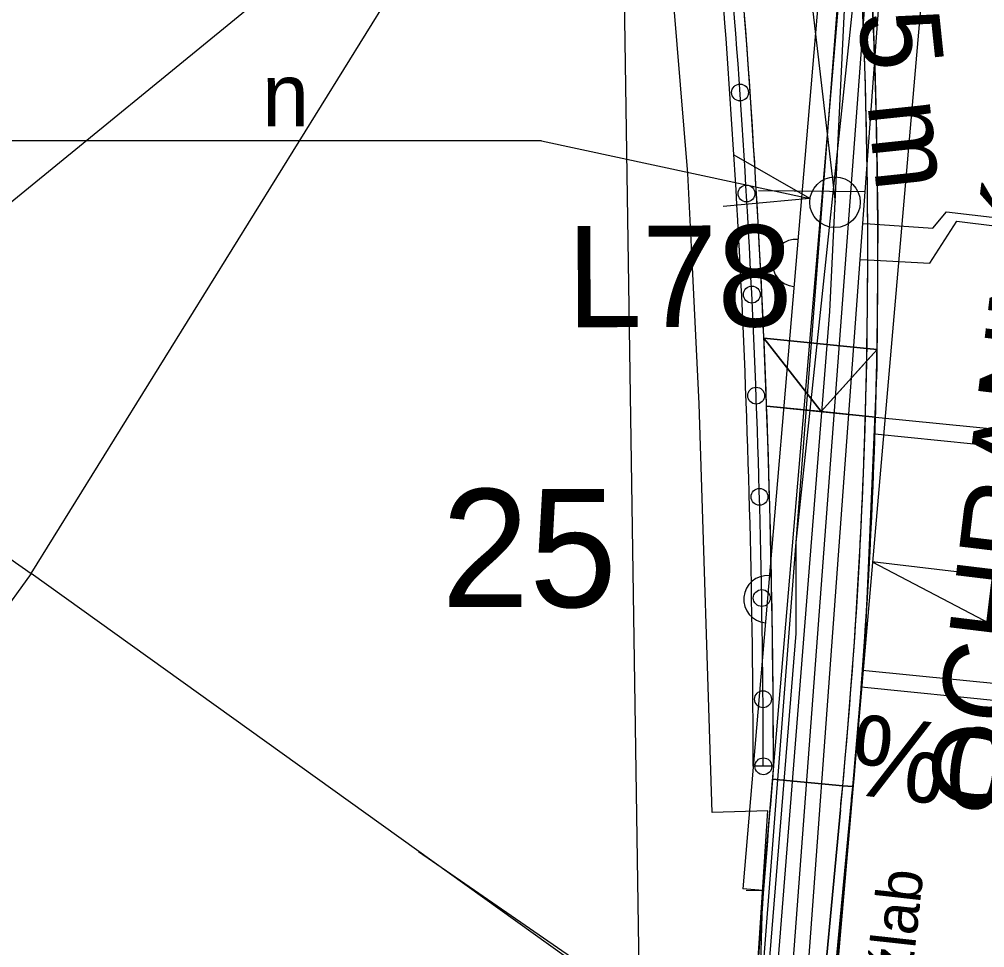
# Model space of a CAD drawing. Extents: x -643342 to -638635, y -1201752 to -1189948.
# Drawn here: x -639509.69 to -639495.38, y -1192753.31 to -1192739.55 of the extents above; entities that cross this region are included whole.
import ezdxf

# ---------------------------------------------------------------- set-up
doc = ezdxf.new("R2010")
doc.units = 0
for name, color, linetype in [('2', 7, 'Continuous'), ('42', 7, 'Continuous'), ('IS_EL_NN_NADZEMNÍ', 7, 'Continuous'), ('IS_EL_NN_PODZEMNÍ', 7, 'Continuous'), ('IS_PLYN_STL', 7, 'Continuous'), ('IS_TELEF_MISTNI_ZAMERENO', 7, 'Continuous'), ('IS_VODOVOD_PRIPOJKA DOMOVNÍ', 7, 'Continuous'), ('IS_VODOVOD_VAS', 7, 'Continuous'), ('K-HRANICE_KN', 7, 'Continuous'), ('K-ČÍSLA_PARCEL', 7, 'Continuous'), ('N-CHODNIK', 7, 'Continuous'), ('N-OBVOD STAVBY 06', 7, 'Continuous'), ('N-oploceni', 7, 'Continuous'), ('N-SILNICE', 7, 'Continuous'), ('N-SO101_KLOPENI', 7, 'Continuous'), ('N-SRAFY_PLOCHY', 7, 'Continuous'), ('RWE_STL_RADY', 7, 'Continuous'), ('tomaštík - Džuganovi - Vrstva 36', 7, 'Continuous'), ('Vrstva 46', 7, 'Continuous'), ('Z-budovy', 7, 'Continuous'), ('Z-hrany_a_čáry', 7, 'Continuous'), ('Z-popisy', 7, 'Continuous'), ('Z-vchody_vjezdy', 7, 'Continuous')]:
    doc.layers.add(name, color=color, linetype=linetype)

# ---------------------------------------------------------------- blocks, each defined once
blk = doc.blocks.new('A$C48307C76')
at = {"layer": 'N-oploceni'}
blk.add_circle((0, 0), 0.125, dxfattribs=at)

msp = doc.modelspace()

# ---------------------------------------------------------------- linework, layer by layer
at = {"layer": '2'}
msp.add_circle((-639497.601, -1192742.26), 0.375, dxfattribs=at)
at = {"layer": '42'}
for p, q in [((-639501.952, -1192741.351), (-639555.598, -1192741.352)), ((-639501.952, -1192741.351), (-639497.972, -1192742.204)), ((-639497.972, -1192742.204), (-639499.096, -1192741.563)), ((-639497.972, -1192742.204), (-639499.261, -1192742.322))]:
    msp.add_line(p, q, dxfattribs=at)
at = {"layer": 'IS_EL_NN_NADZEMNÍ'}
msp.add_line((-639500.77, -1192736.43), (-639500.31, -1192766.84), dxfattribs=at)
at = {"layer": 'IS_EL_NN_PODZEMNÍ'}
msp.add_line((-639501.46, -1192735.43), (-639513.06, -1192744.91), dxfattribs=at)
at = {"layer": 'IS_PLYN_STL'}
msp.add_lwpolyline([(-639501.39, -1192783.75), (-639500.989, -1192780.093), (-639500.16, -1192772.52), (-639499.45, -1192766.45), (-639499.2, -1192762.17), (-639498.55, -1192754.89), (-639497.68, -1192743.88), (-639497.18, -1192733.61), (-639497.87, -1192731.06), (-639499.7, -1192729.08), (-639500.91, -1192728.3), (-639501.94, -1192727.99), (-639507.97, -1192726.09), (-639511.7, -1192724.84), (-639512.15, -1192724.73), (-639515.02, -1192723.8), (-639520.31, -1192722.34), (-639520.46, -1192722.3), (-639520.92, -1192722.11)], dxfattribs=at)
at = {"layer": 'IS_TELEF_MISTNI_ZAMERENO'}
for p, q in [((-639497.15, -1192737.53), (-639498.18, -1192747.3)), ((-639497.15, -1192737.53), (-639498.18, -1192747.3)), ((-639498.18, -1192747.3), (-639498.18, -1192748.65)), ((-639498.18, -1192748.65), (-639499.13, -1192760.28)), ((-639498.18, -1192748.65), (-639499.13, -1192760.28))]:
    msp.add_line(p, q, dxfattribs=at)
at = {"layer": 'IS_VODOVOD_PRIPOJKA DOMOVNÍ'}
for points in [[(-639497.153, -1192742.104), (-639498.734, -1192742.093)], [(-639497.188, -1192742.573), (-639497.08, -1192742.58), (-639496.151, -1192742.644), (-639495.95, -1192742.4), (-639489.396, -1192743.168), (-639488.439, -1192743.166)], [(-639497.227, -1192743.11), (-639497.02, -1192743.12), (-639496.196, -1192743.161), (-639495.797, -1192742.541), (-639488.178, -1192743.486)]]:
    msp.add_lwpolyline(points, dxfattribs=at)
at = {"layer": 'IS_VODOVOD_VAS'}
for points in [[(-639513.05, -1192632.38), (-639511.6, -1192653.11), (-639509.94, -1192661.802), (-639509.17, -1192665.92), (-639508.128, -1192674.317), (-639507.037, -1192678.26), (-639504.087, -1192695.682), (-639502.448, -1192705.362), (-639494.166, -1192711.159), (-639494.54, -1192716.007), (-639495.94, -1192729.045), (-639496.55, -1192731.72), (-639496.617, -1192732.012), (-639498.895, -1192762.442), (-639502.42, -1192797.68), (-639508.622, -1192858.606)], [(-639508.361, -1192858.606), (-639507.808, -1192853.178), (-639506.048, -1192835.895), (-639505.024, -1192825.834), (-639502.574, -1192801.785), (-639502.3, -1192799.09), (-639501.659, -1192792.67), (-639499.852, -1192774.557), (-639499.821, -1192774.244), (-639499.787, -1192773.906), (-639498.645, -1192762.458), (-639497.227, -1192743.11), (-639497.188, -1192742.573), (-639497.153, -1192742.104), (-639496.521, -1192733.479), (-639496.454, -1192733.187), (-639495.873, -1192730.664), (-639495.841, -1192730.366)]]:
    msp.add_lwpolyline(points, dxfattribs=at)
at = {"layer": 'K-HRANICE_KN'}
for p, q in [((-639509.52, -1192747.76), (-639501.41, -1192734.7)), ((-639497.4, -1192737.18), (-639498.81, -1192755.44)), ((-639519.51, -1192740.84), (-639509.52, -1192747.76)), ((-639509.52, -1192747.76), (-639513.27, -1192752.94)), ((-639499.75, -1192754.76), (-639509.52, -1192747.76))]:
    msp.add_line(p, q, dxfattribs=at)
at = {"layer": 'N-CHODNIK'}
for p, q in [((-639497.001, -1192745.444), (-639490.369, -1192746.106)), ((-639497.008, -1192745.694), (-639490.394, -1192746.355)), ((-639497.193, -1192749.193), (-639490.742, -1192749.837)), ((-639497.211, -1192749.443), (-639490.767, -1192750.086))]:
    msp.add_line(p, q, dxfattribs=at)
at = {"layer": 'N-OBVOD STAVBY 06'}
msp.add_lwpolyline([(-639501.67, -1192780.46), (-639501.67, -1192780.46), (-639500.56, -1192772.43), (-639500.37, -1192770.844), (-639499.75, -1192766.35), (-639501.075, -1192766.21), (-639500.65, -1192762.336), (-639499.361, -1192762.432), (-639499.064, -1192758.144), (-639498.745, -1192753.539), (-639498.595, -1192751.279), (-639498.595, -1192751.279), (-639499.424, -1192751.305), (-639499.616, -1192745.247), (-639499.725, -1192743.019), (-639499.783, -1192741.836), (-639500.319, -1192735.379)], dxfattribs=at)
at = {"layer": 'N-oploceni'}
msp.add_arc((-639647.046, -1192750.754), 148.382, 0.05221, 5.64877, dxfattribs=at)
at = {"layer": 'N-SILNICE'}
for p, q in [((-639498.655, -1192744.274), (-639496.978, -1192744.441)), ((-639498.655, -1192744.274), (-639497.807, -1192745.363)), ((-639497.807, -1192745.363), (-639496.978, -1192744.441)), ((-639498.614, -1192745.283), (-639497.001, -1192745.444)), ((-639498.513, -1192750.619), (-639498.813, -1192750.619)), ((-639498.529, -1192750.808), (-639497.338, -1192750.919)), ((-639497.924, -1192755.578), (-639497.521, -1192751.267)), ((-639497.774, -1192755.592), (-639497.372, -1192751.281))]:
    msp.add_line(p, q, dxfattribs=at)
for centre, radius, start, end in [((-639581.965, -1192742.977), 85, 354.39361, 9.47307), ((-639581.965, -1192742.977), 84.85, 354.39361, 5.48049), ((-639581.965, -1192742.977), 85, 354.39361, 5.48049), ((-639647.046, -1192750.754), 148.532, 0.05221, 6.02687), ((-639647.046, -1192750.754), 148.232, 0.05221, 5.61695), ((-639118.057, -1192782.226), 381.767, 175.25099, 176.38348)]:
    msp.add_arc(centre, radius, start, end, dxfattribs=at)
at = {"layer": 'N-SO101_KLOPENI'}
msp.add_lwpolyline([(-639493.797, -1192747.973), (-639497.052, -1192747.591), (-639493.944, -1192749.215), (-639493.797, -1192747.973)], close=True, dxfattribs=at)
at = {"layer": 'N-SRAFY_PLOCHY'}
for p, q in [((-639497.087, -1192738.46), (-639497.005, -1192740.394)), ((-639497.005, -1192740.394), (-639496.966, -1192742.5)), ((-639496.966, -1192742.5), (-639496.982, -1192744.715)), ((-639498.655, -1192744.274), (-639497.127, -1192744.426)), ((-639497.127, -1192744.426), (-639498.655, -1192744.274)), ((-639496.978, -1192744.441), (-639497.131, -1192744.611)), ((-639497.131, -1192744.611), (-639496.978, -1192744.441)), ((-639497.127, -1192744.426), (-639496.978, -1192744.441)), ((-639496.978, -1192744.441), (-639497.127, -1192744.426)), ((-639497.131, -1192744.611), (-639497.807, -1192745.363)), ((-639496.982, -1192744.715), (-639497.148, -1192748.595)), ((-639497.807, -1192745.363), (-639498.614, -1192745.283)), ((-639497.15, -1192745.429), (-639497.807, -1192745.363)), ((-639497.807, -1192745.363), (-639497.15, -1192745.429)), ((-639497.15, -1192745.429), (-639497.001, -1192745.444)), ((-639497.001, -1192745.444), (-639497.15, -1192745.429)), ((-639497.148, -1192748.595), (-639497.317, -1192750.745)), ((-639498.529, -1192750.808), (-639497.486, -1192750.906)), ((-639497.486, -1192750.906), (-639498.529, -1192750.808)), ((-639497.317, -1192750.745), (-639497.536, -1192753.086)), ((-639497.486, -1192750.906), (-639497.337, -1192750.92)), ((-639497.337, -1192750.92), (-639497.486, -1192750.906)), ((-639497.536, -1192753.086), (-639497.808, -1192755.996))]:
    msp.add_line(p, q, dxfattribs=at)
for points in [[(-639498.614, -1192745.283), (-639497.807, -1192745.363), (-639498.655, -1192744.274)], [(-639498.655, -1192744.274), (-639497.807, -1192745.363), (-639497.131, -1192744.611)], [(-639498.837, -1192754.797), (-639497.859, -1192754.888), (-639497.521, -1192751.266)], [(-639497.521, -1192751.266), (-639497.859, -1192754.888), (-639497.71, -1192754.902), (-639497.372, -1192751.281)]]:
    msp.add_lwpolyline(points, dxfattribs=at)
for centre, radius, start, end in [((-639581.965, -1192742.977), 84.85, 359.02114, 5.48049), ((-639581.965, -1192742.977), 84.85, 359.02114, 5.48049), ((-639581.965, -1192742.977), 85, 359.01279, 5.48049), ((-639647.046, -1192750.754), 148.532, 2.50056, 6.02687), ((-639647.046, -1192750.754), 148.532, 2.11102, 2.50056), ((-639581.965, -1192742.977), 84.85, 358.89613, 359.02114), ((-639581.965, -1192742.977), 84.85, 358.89613, 359.02114), ((-639581.965, -1192742.977), 85, 358.33674, 359.01279), ((-639581.965, -1192742.977), 84.85, 358.34389, 358.89613), ((-639581.965, -1192742.977), 84.85, 358.34389, 358.89613), ((-639647.046, -1192750.754), 148.532, 0.05221, 2.11102), ((-639581.965, -1192742.977), 84.85, 354.63801, 358.34389), ((-639581.965, -1192742.977), 84.85, 354.63801, 358.34389), ((-639581.965, -1192742.977), 85, 354.63805, 358.33674), ((-639118.057, -1192782.226), 381.767, 175.25099, 175.27954), ((-639118.057, -1192782.226), 381.767, 175.27954, 175.87994), ((-639581.965, -1192742.977), 84.85, 354.39337, 354.63801), ((-639581.965, -1192742.977), 84.85, 354.39337, 354.63801), ((-639581.965, -1192742.977), 85, 354.39361, 354.63805)]:
    msp.add_arc(centre, radius, start, end, dxfattribs=at)
at = {"layer": 'RWE_STL_RADY'}
msp.add_lwpolyline([(-639502.076, -1192726.369), (-639502.112, -1192726.754), (-639498.698, -1192732.892), (-639497.601, -1192742.26)], dxfattribs=at)
at = {"layer": 'Z-budovy'}
msp.add_line((-639503.777, -1192751.883), (-639499.66, -1192754.72), dxfattribs=at)
at = {"layer": 'Z-hrany_a_čáry'}
for p, q in [((-639495.99, -1192735.46), (-639497.82, -1192756.55)), ((-639497.38, -1192737.29), (-639498.67, -1192752.46)), ((-639497.694, -1192737.443), (-639498.969, -1192752.435)), ((-639498.67, -1192752.46), (-639498.969, -1192752.435))]:
    msp.add_line(p, q, dxfattribs=at)
for centre in [(-639498.18, -1192743.16), (-639498.604, -1192748.142)]:
    msp.add_arc(centre, 0.35, 85.139, 265.139, dxfattribs=at)
at = {"layer": 'Z-vchody_vjezdy'}
for p in [(-639498.92, -1192752.453), (-639498.7, -1192753.54)]:
    msp.add_line(p, (-639498.67, -1192752.46), dxfattribs=at)

# ---------------------------------------------------------------- block references
at = {"layer": 'defpoints'}
for p, rotation in [((-639499.009, -1192740.633), 93.91115389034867), ((-639498.914, -1192742.13), 93.3319500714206), ((-639498.835, -1192743.628), 92.75274625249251), ((-639498.77, -1192745.126), 92.17354243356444), ((-639498.721, -1192746.626), 91.59433861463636), ((-639498.687, -1192748.125), 91.01513479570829), ((-639498.668, -1192749.625), 90.43593097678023), ((-639498.663, -1192750.619), 90.43593097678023)]:
    msp.add_blockref('A$C48307C76', p, dxfattribs=dict(at, rotation=rotation))

# ---------------------------------------------------------------- texts
at = {"layer": 'K-ČÍSLA_PARCEL'}
msp.add_text('25', height=1.75, dxfattribs=at).set_placement((-639503.437, -1192748.26))
at = {"layer": 'N-SO101_KLOPENI'}
msp.add_text('2.50%', height=1.2, rotation=173.3259, dxfattribs=at).set_placement((-639492.774, -1192750.362))
at = {"layer": 'RWE_STL_RADY'}
msp.add_text('STLPE 90 - 16,85 m', height=1.2, rotation=276.0055, dxfattribs=at).set_placement((-639498.503, -1192727.668))
at = {"layer": 'tomaštík - Džuganovi - Vrstva 36'}
for s, height, rotation, p in [('OCHRANNÁ TRUBKA ', 1.25, 83.0956, (-639494.978, -1192751.335)), ('n', 0.938, 0.0307, (-639506.096, -1192741.137))]:
    msp.add_text(s, height=height, rotation=rotation, dxfattribs=at).set_placement(p)
at = {"layer": 'Vrstva 46'}
msp.add_text('L78', height=1.5, rotation=0.301, dxfattribs=at).set_placement((-639501.574, -1192744.115))
at = {"layer": 'Z-popisy'}
msp.add_text('bet. žlab', height=0.65, rotation=83.7271, dxfattribs=at).set_placement((-639496.647, -1192755.444))

doc.saveas('drawing.dxf')
